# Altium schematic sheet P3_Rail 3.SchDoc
size 368 x 228 mm
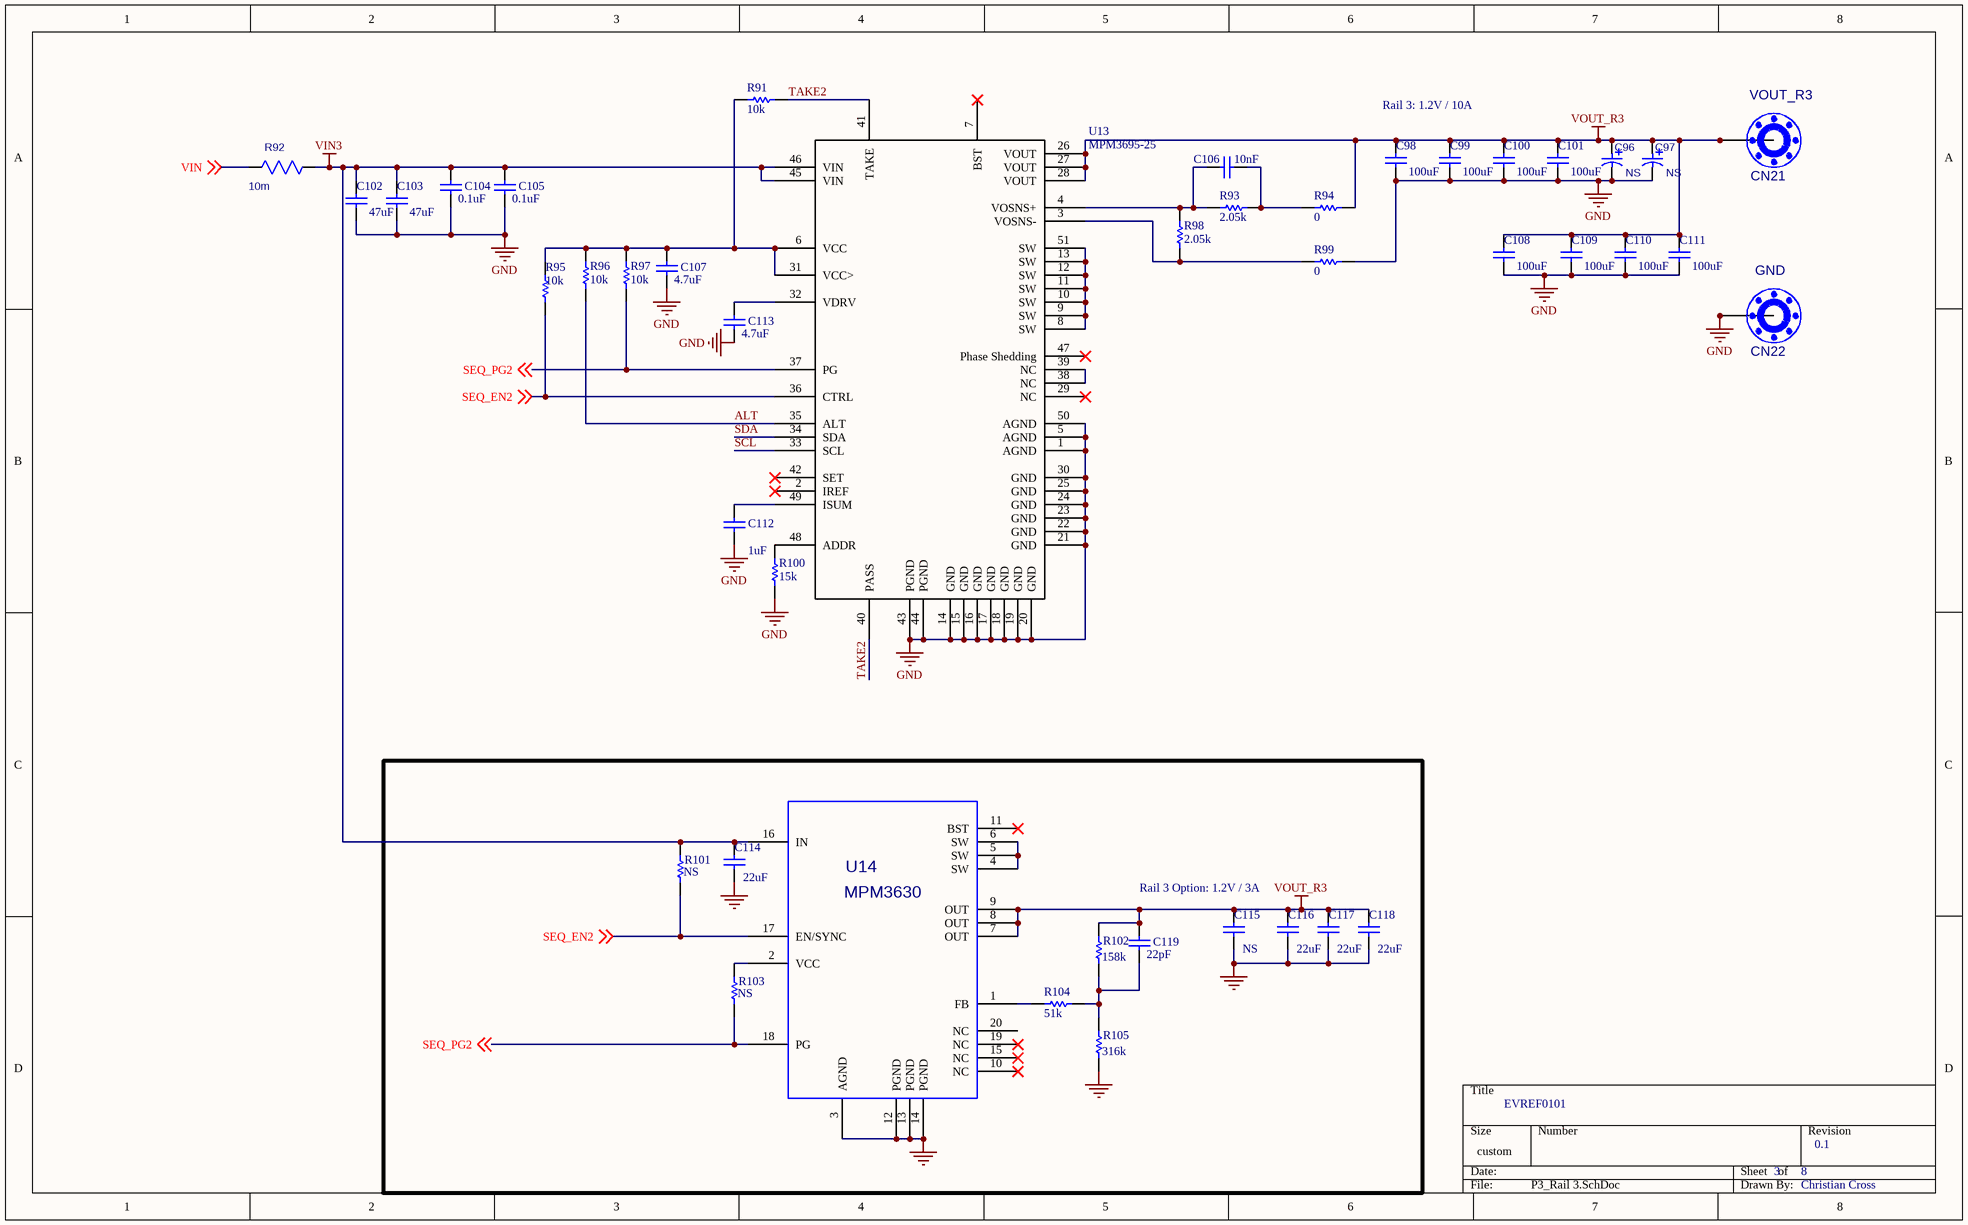
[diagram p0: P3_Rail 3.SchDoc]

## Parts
C96  value NS  [POSCAP/D2]  (hidden comment: POSCAP/D2-D4)
C97  value NS  [POSCAP/D2]  (hidden comment: POSCAP/D2-D4)
C98  100uF  [CAP/1210]
C99  100uF  [CAP/1210]
C100  100uF  [CAP/1210]
C101  100uF  [CAP/1210]
C102  47uF  [CAP/1210]
C103  47uF  [CAP/1210]
C104  0.1uF  [CAP0402]
C105  0.1uF  [CAP0402]
C106  10nF  [CAP0603]
C107  4.7uF  [CAP/0603]
C108  100uF  [CAP/1210]
C109  100uF  [CAP/1210]
C110  100uF  [CAP/1210]
C111  100uF  [CAP/1210]
C112  1uF  [CAP/0603]
C113  value 4.7uF  [CAP/0603]  (hidden comment: 5.6pF/CAP0603)
C114  22uF  [CAP0805]
C115  NS  [CAP0805]
C116  value 22uF  [CAP0805]  (hidden comment: Cap)
C117  value 22uF  [CAP0805]  (hidden comment: Cap)
C118  value 22uF  [CAP0805]  (hidden comment: Cap)
C119  22pF  [CAP/0603]
CN21  VOUT_R3  [BANANA-K575]
CN22  GND  [BANANA-K575]
R91  10k  [RES/0603]
R92  10m  [RES2512]
R93  2.05k  [RES/0603]
R94  0  [RES/0603]
R95  10k  [RES/0603]
R96  10k  [RES/0603]
R97  10k  [RES/0603]
R98  2.05k  [RES/0603]
R99  0  [RES/0603]
R100  15k  [RES0603]
R101  NS  [RES/0603]
R102  158k  [RES0603]
R103  NS  [RES/0603]
R104  51k  [RES0603]
R105  316k  [RES0603]
U13  MPM3695-25  [MPM3695-25 - ROY]
U14  Manufacturer P/N: MPM3630  [QFN20-3X5MM]  (hidden comment: MPM3630A)

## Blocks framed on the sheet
Rail 3 Option: 1.2V / 3A: C114-C119 R101-R105 U14

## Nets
GND: C96.2 C97.2 C98.1 C99.1 C100.1 C101.1 C102.1 C103.1 C104.1 C105.1 C107.1 C108.1 C109.1 C110.1 C111.1 C112.1 C113.1 C114.1 C115.1 C116.1 C117.1 C118.1 CN22.1 CN22.2 CN22.3 CN22.4 CN22.5 CN22.6 CN22.7 CN22.8 CN22.9 R99.1 R100.2 R105.1 U13.1(AGND) U13.5(AGND) U13.14(GND) U13.15(GND) U13.16(GND) U13.17(GND) U13.18(GND) U13.19(GND) U13.20(GND) U13.21(GND) U13.22(GND) U13.23(GND) U13.24(GND) U13.25(GND) U13.30(GND) U13.43(PGND) U13.44(PGND) U13.50(AGND) U14.3(AGND) U14.12(PGND) U14.13(PGND) U14.14(PGND)
VIN3: C102.2 C103.2 C104.2 C105.2 C114.2 R92.2 R101.2 U13.45(VIN) U13.46(VIN) U14.16(IN)
VOUT_R3: C96.1 C97.1 C98.2 C99.2 C100.2 C101.2 C108.2 C109.2 C110.2 C111.2 C115.2 C116.2 C117.2 C118.2 C119.2 CN21.1 CN21.2 CN21.3 CN21.4 CN21.5 CN21.6 CN21.7 CN21.8 CN21.9 R94.1 R102.2 U13.26(VOUT) U13.27(VOUT) U13.28(VOUT) U14.7(OUT) U14.8(OUT) U14.9(OUT)
ALT: R96.1 U13.35(ALT)
SCL: U13.33(SCL)
SDA: U13.34(SDA)
SEQ_EN2: R95.1 R101.1 U13.36(CTRL) U14.17(EN/SYNC) ; off-sheet SEQ_EN2
SEQ_PG2: R97.2 R103.1 U13.37(PG) U14.18(PG) ; off-sheet SEQ_PG2
TAKE2: R91.1 U13.40(PASS) U13.41(TAKE)
VIN: R92.1 ; off-sheet VIN
NetC106_1: C106.1 R93.2 R98.1 U13.4(VOSNS+)
NetC106_2: C106.2 R93.1 R94.2
NetC107_2: C107.2 R91.2 R95.2 R96.2 R97.1 U13.6(VCC) U13.31(VCC>)
NetC112_2: C112.2 U13.49(ISUM)
NetC113_2: C113.2 U13.32(VDRV)
NetC119_1: C119.1 R102.1 R104.1 R105.2
NetR98_2: R98.2 R99.2 U13.3(VOSNS-)
NetR100_1: R100.1 U13.48(ADDR)
NetR103_2: R103.2 U14.2(VCC)
NetR104_2: R104.2 U14.1(FB)
NetU13_8: U13.8(SW) U13.9(SW) U13.10(SW) U13.11(SW) U13.12(SW) U13.13(SW) U13.51(SW)
NetU13_38: U13.38(NC) U13.39(NC)
NetU14_4: U14.4(SW) U14.5(SW) U14.6(SW)

Not connected (* = marked no-connect by the designer): U13 2(IREF)* 7(BST)* 29(NC)* 42(SET)* 47(Phase_Shedding)*; U14 10(NC)* 11(BST)* 15(NC)* 19(NC)* 20(NC)

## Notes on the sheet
- Rail 3: 1.2V / 10A
- EVREF0101
- 3
- 8
- 0.1
- Christian Cross

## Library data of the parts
C96 C97 = POSCAP/D2-D4: {Description}; Manufacturer P/N: {Manufacturer P/N}; Manufacturer: {Manufacturer}
C98-C119 = Cap: Capacitor
CN21 CN22 = BANANA-K575: Connector, RCA Jack, R/A; Manufacturer P/N: RCJ-012; Manufacturer: CUI, Inc.
R91 R93 R95-R98 R100-R105 = Res1: Resistor
R92 = RES2512: {Description}; Manufacturer P/N: {Manufacturer P/N}; Manufacturer: {Manufacturer}
R94 R99 = Res1: Resistor; Value: 0ohm
U14 = MPM3630A: 18V/3A DC/DC Module Synchronous Step-Down Regulator; Manufacturer: {Manufacturer}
